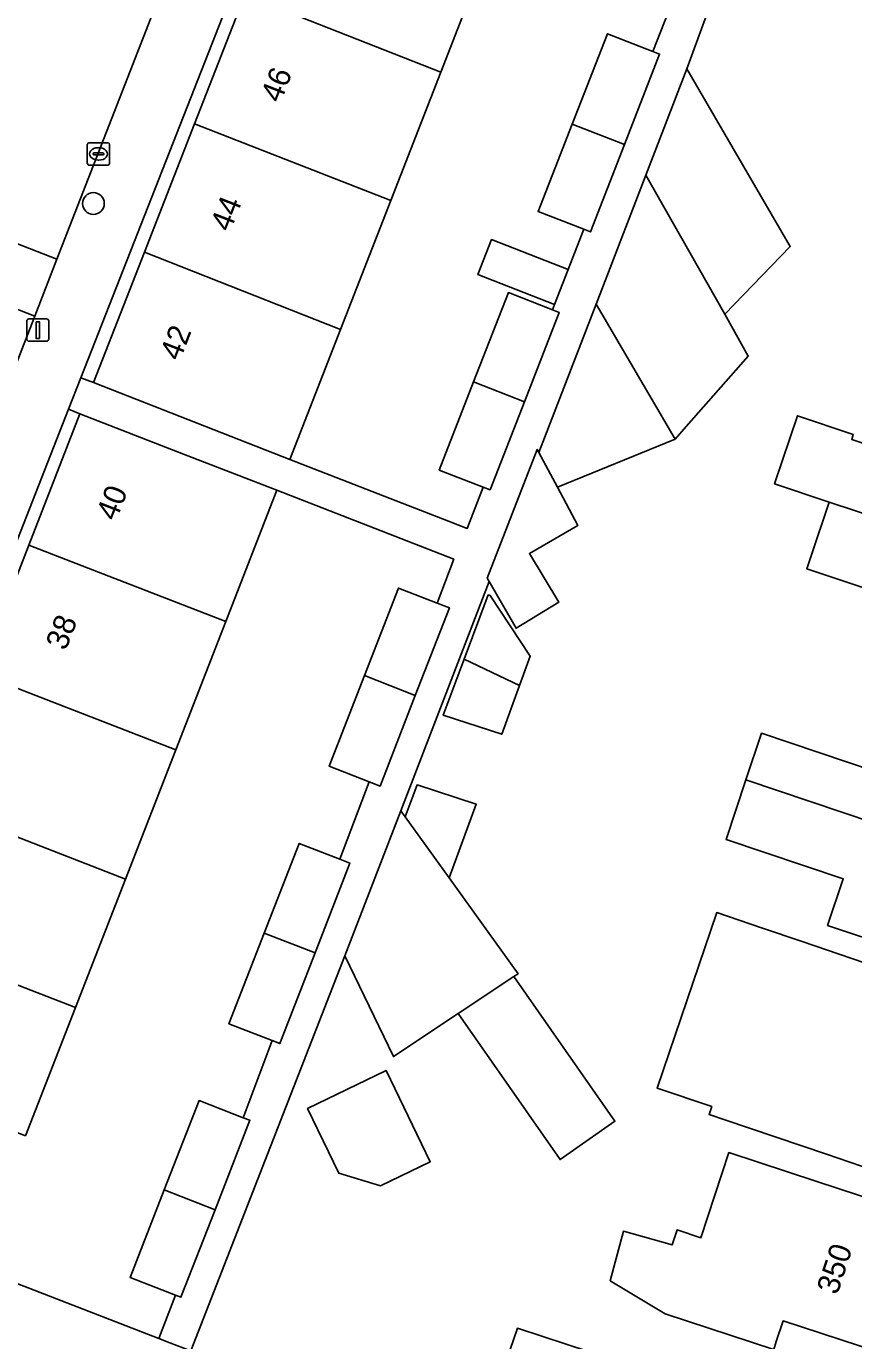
# Model space of a CAD drawing. Extents: x 161248 to 161848, y 384871 to 385383.
# Drawn here: x 161640.1 to 161677.3, y 385139.3 to 385198.5 of the extents above; entities that cross this region are included whole.
import ezdxf

# ---------------------------------------------------------------- set-up
doc = ezdxf.new("R2010")
doc.units = 0
for name, color, linetype in [('IMGEO_Boom', 7, 'Continuous'), ('IMGEO_Erf', 7, 'Continuous'), ('IMGEO_Kolk', 7, 'Continuous'), ('IMGEO_Lichtmast', 7, 'Continuous'), ('IMGEO_Pand', 7, 'Continuous'), ('IMGEO_Pand_nummerreeks', 7, 'Continuous'), ('IMGEO_Rijbaan_lokaal_open', 7, 'Continuous'), ('IMGEO_Voetpad_open', 7, 'Continuous')]:
    doc.layers.add(name, color=color, linetype=linetype)

msp = doc.modelspace()

# ---------------------------------------------------------------- linework, layer by layer
at = {"layer": 'IMGEO_Boom'}
msp.add_circle((161643.079, 385190.484), 0.489, dxfattribs=at)
at = {"layer": 'IMGEO_Erf'}
for points in [[(161654.386, 385211.393), (161656.644, 385217.179), (161658.899, 385222.955), (161661.19, 385228.826), (161658.366, 385229.85), (161658.187, 385226.898), (161657.602, 385223.032), (161656.675, 385219.233), (161655.412, 385215.533), (161642.519, 385182.649), (161643.081, 385182.429), (161645.371, 385188.297), (161647.622, 385194.063), (161649.884, 385199.859), (161652.083, 385205.494)], [(161637.929, 385169.353), (161640.175, 385175.123), (161642.475, 385181.032), (161641.964, 385181.232), (161628.283, 385146.338), (161628.877, 385146.101), (161631.173, 385151.999), (161633.419, 385157.768), (161635.668, 385163.546)], [(161662.244, 385168.813), (161661.44, 385166.618), (161658.808, 385167.475), (161659.748, 385169.996), (161660.827, 385172.886), (161660.921, 385172.851), (161662.724, 385170.122)], [(161656.239, 385151.494), (161658.225, 385147.394), (161655.988, 385146.311), (161654.119, 385146.88), (161652.712, 385149.785)]]:
    msp.add_lwpolyline(points, close=True, dxfattribs=at)
for points in [[(161675.04, 385210.948), (161669.768, 385196.541), (161674.417, 385188.547), (161671.465, 385185.506), (161672.515, 385183.615), (161669.733, 385180.456), (161669.236, 385179.891), (161663.947, 385177.724), (161664.866, 385176.006), (161662.688, 385174.743), (161664.001, 385172.555), (161662.085, 385171.383), (161660.87, 385173.48), (161656.896, 385163.18), (161657.099, 385162.898), (161657.636, 385164.335), (161660.29, 385163.477), (161659.073, 385160.158), (161662.176, 385155.85), (161661.989, 385155.726), (161666.53, 385149.215), (161664.061, 385147.492), (161659.481, 385154.059), (161656.566, 385152.122), (161654.38, 385156.66), (161647.453, 385138.885)], [(161660.94, 385202.148), (161658.696, 385196.386), (161656.448, 385190.614), (161654.193, 385184.823), (161651.916, 385178.978), (161659.042, 385176.194), (161659.88, 385175.866), (161660.608, 385177.73), (161658.632, 385178.499), (161660.177, 385182.466), (161661.739, 385186.476), (161663.723, 385185.703), (161663.816, 385185.941), (161660.368, 385187.284), (161660.983, 385188.864), (161664.431, 385187.521), (161665.132, 385189.323), (161663.077, 385190.123), (161664.609, 385194.056), (161666.191, 385198.118), (161668.241, 385197.319), (161669.584, 385200.772)], [(161680.453, 385172.283), (161675.16, 385174.052), (161675.327, 385174.553), (161676.163, 385177.056), (161673.709, 385177.876), (161674.732, 385180.937), (161677.249, 385180.096), (161677.175, 385179.873), (161682.375, 385178.135)], [(161637.729, 385142.655), (161646.017, 385139.442), (161646.773, 385141.392), (161644.734, 385142.186), (161646.268, 385146.127), (161647.832, 385150.145), (161649.815, 385149.373), (161651.114, 385152.845), (161649.176, 385153.599), (161650.764, 385157.677), (161652.334, 385161.709), (161654.164, 385160.996), (161655.481, 385164.475), (161653.683, 385165.175), (161655.271, 385169.254), (161656.803, 385173.19), (161658.533, 385172.517), (161659.281, 385174.489), (161651.327, 385177.586), (161649.028, 385171.681), (161646.782, 385165.911), (161644.522, 385160.104), (161642.272, 385154.325), (161640.026, 385148.555)], [(161679.112, 385157.009), (161676.089, 385158.024), (161676.793, 385160.12), (161671.526, 385161.889), (161672.423, 385164.561), (161673.128, 385166.659), (161678.281, 385164.927)], [(161680.771, 385146.118), (161676.038, 385147.728), (161671.476, 385149.279), (161670.764, 385149.522), (161670.883, 385149.872), (161668.426, 385150.708), (161671.111, 385158.6), (161673.114, 385157.918), (161674.951, 385157.293), (161678.841, 385155.97)], [(161673.673, 385138.958), (161668.79, 385140.562), (161666.321, 385142.043), (161666.91, 385144.269), (161667.285, 385144.164), (161669.102, 385143.655), (161669.323, 385144.33), (161670.397, 385143.977), (161671.654, 385147.805), (161675.604, 385146.508), (161680.354, 385144.948)], [(161661.28, 385137.38), (161662.143, 385139.909), (161667.621, 385138.111)], [(161678.348, 385138.839), (161674.092, 385140.237), (161673.787, 385139.306)]]:
    msp.add_lwpolyline(points, dxfattribs=at)
at = {"layer": 'IMGEO_Kolk'}
for p, q in [((161642.806, 385192.286), (161642.806, 385193.138)), ((161642.881, 385193.212), (161643.733, 385193.212)), ((161643.294, 385192.992), (161643.319, 385192.992)), ((161643.807, 385193.138), (161643.807, 385192.286)), ((161643.065, 385192.706), (161643.065, 385192.718)), ((161643.503, 385192.669), (161643.105, 385192.669)), ((161643.108, 385192.755), (161643.506, 385192.755)), ((161643.317, 385192.432), (161643.292, 385192.432)), ((161643.549, 385192.718), (161643.549, 385192.706)), ((161643.733, 385192.212), (161642.881, 385192.212))]:
    msp.add_line(p, q, dxfattribs=at)
for points in [[(161642.806, 385192.286), (161642.806, 385193.138)], [(161642.881, 385193.212), (161643.733, 385193.212)], [(161643.807, 385193.138), (161643.807, 385192.286)], [(161643.733, 385192.212), (161642.881, 385192.212)]]:
    msp.add_lwpolyline(points, dxfattribs=at)
for centre, radius, start, end in [((161642.883, 385193.136), 0.0765, 91.55205, 178.44795), ((161642.883, 385193.136), 0.0765, 91.55205, 178.44795), ((161643.731, 385193.136), 0.0765, 1.55205, 88.44795), ((161643.731, 385193.136), 0.0765, 1.55205, 88.44795), ((161643.105, 385192.715), 0.0403, 85.87752, 175.75265), ((161643.102, 385192.705), 0.0366, 178.93798, 274.71019), ((161643.506, 385192.712), 0.043, 264.86636, 352.45326), ((161643.51, 385192.717), 0.0386, 1.73085, 96.63898), ((161642.883, 385192.288), 0.0765, 181.55205, 268.44795), ((161642.883, 385192.288), 0.0765, 181.55205, 268.44795), ((161643.731, 385192.288), 0.0765, 271.55205, 358.44795), ((161643.731, 385192.288), 0.0765, 271.55205, 358.44795)]:
    msp.add_arc(centre, radius, start, end, dxfattribs=at)
for centre, major_axis, ratio, start_param, end_param in [((161643.293, 385192.712), (-0.387, 0.002), 0.722429, 4.712389, 7.853982), ((161643.318, 385192.712), (-0.39, 0.002), 0.717154, 1.570796, 4.712389)]:
    msp.add_ellipse(centre, major_axis=major_axis, ratio=ratio, start_param=start_param, end_param=end_param, dxfattribs=at)
at = {"layer": 'IMGEO_Lichtmast'}
for p, q in [((161640.182, 385185.292), (161640.972, 385185.292)), ((161640.972, 385185.292), (161640.182, 385185.292)), ((161640.082, 385184.392), (161640.082, 385185.192)), ((161640.082, 385185.192), (161640.082, 385184.392)), ((161641.072, 385185.192), (161641.072, 385184.392)), ((161641.072, 385184.392), (161641.072, 385185.192)), ((161640.972, 385184.292), (161640.182, 385184.292)), ((161640.182, 385184.292), (161640.972, 385184.292))]:
    msp.add_line(p, q, dxfattribs=at)
msp.add_lwpolyline([(161640.502, 385185.167), (161640.652, 385185.167), (161640.652, 385184.417), (161640.502, 385184.417), (161640.502, 385185.167)], dxfattribs=at)
for centre, start, end in [((161640.182, 385185.192), 90, 180), ((161640.182, 385185.192), 90, 180), ((161640.972, 385185.192), 0, 90), ((161640.972, 385185.192), 360, 90), ((161640.182, 385184.392), 180, 270), ((161640.182, 385184.392), 180, 270), ((161640.972, 385184.392), 270, 0), ((161640.972, 385184.392), 270, 0)]:
    msp.add_arc(centre, 0.1, start, end, dxfattribs=at)
at = {"layer": 'IMGEO_Pand'}
for points in [[(161652.083, 385205.494), (161649.884, 385199.859), (161658.696, 385196.386), (161660.94, 385202.148)], [(161656.448, 385190.614), (161658.696, 385196.386), (161649.884, 385199.859), (161647.622, 385194.063)], [(161668.241, 385197.319), (161666.191, 385198.118), (161664.609, 385194.056), (161666.954, 385193.131), (161668.539, 385197.203)], [(161671.465, 385185.506), (161674.417, 385188.547), (161669.768, 385196.541), (161667.922, 385191.755)], [(161647.622, 385194.063), (161645.371, 385188.297), (161654.193, 385184.823), (161656.448, 385190.614)], [(161666.954, 385193.131), (161664.609, 385194.056), (161663.077, 385190.123), (161665.132, 385189.323), (161665.426, 385189.208)], [(161667.922, 385191.755), (161666.013, 385186.808), (161665.684, 385185.956), (161669.236, 385179.891), (161669.733, 385180.456), (161672.515, 385183.615), (161671.465, 385185.506)], [(161664.431, 385187.521), (161660.983, 385188.864), (161660.368, 385187.284), (161663.816, 385185.941)], [(161645.371, 385188.297), (161643.081, 385182.429), (161647.739, 385180.61), (161651.916, 385178.978), (161654.193, 385184.823)], [(161663.723, 385185.703), (161661.739, 385186.476), (161660.177, 385182.466), (161662.459, 385181.568), (161664.024, 385185.586)], [(161669.236, 385179.891), (161665.684, 385185.956), (161663.111, 385179.288), (161663.947, 385177.724)], [(161662.459, 385181.568), (161660.177, 385182.466), (161658.632, 385178.499), (161660.608, 385177.73), (161660.918, 385177.609)], [(161691.577, 385178.551), (161686.835, 385180.135), (161683.424, 385181.275), (161682.375, 385178.135), (161677.175, 385179.873), (161677.249, 385180.096), (161674.732, 385180.937), (161673.709, 385177.876), (161676.163, 385177.056), (161689.598, 385172.63)], [(161649.028, 385171.681), (161651.327, 385177.586), (161647.135, 385179.218), (161642.475, 385181.032), (161640.175, 385175.123)], [(161663.947, 385177.724), (161663.111, 385179.288), (161663.036, 385179.428), (161660.78, 385173.636), (161660.87, 385173.48), (161662.085, 385171.383), (161664.001, 385172.555), (161662.688, 385174.743), (161664.866, 385176.006)], [(161689.598, 385172.63), (161676.163, 385177.056), (161675.327, 385174.553), (161675.16, 385174.052), (161680.453, 385172.283), (161679.498, 385169.423), (161682.877, 385168.294), (161687.619, 385166.709)], [(161640.175, 385175.123), (161637.929, 385169.353), (161646.782, 385165.911), (161649.028, 385171.681)], [(161658.533, 385172.517), (161656.803, 385173.19), (161655.271, 385169.254), (161657.555, 385168.366), (161659.087, 385172.301)], [(161660.827, 385172.886), (161659.748, 385169.996), (161662.244, 385168.813), (161662.724, 385170.122), (161660.921, 385172.851)], [(161662.244, 385168.813), (161659.748, 385169.996), (161658.808, 385167.475), (161661.44, 385166.618)], [(161644.522, 385160.104), (161646.782, 385165.911), (161637.929, 385169.353), (161635.668, 385163.546)], [(161657.555, 385168.366), (161655.271, 385169.254), (161653.683, 385165.175), (161655.481, 385164.475), (161655.967, 385164.286)], [(161687.053, 385164.948), (161682.314, 385166.54), (161679.177, 385167.594), (161678.281, 385164.927), (161673.128, 385166.659), (161672.423, 385164.561), (161685.452, 385160.182)], [(161685.452, 385160.182), (161672.423, 385164.561), (161671.526, 385161.889), (161676.793, 385160.12), (161676.089, 385158.024), (161679.112, 385157.009), (161683.851, 385155.417)], [(161660.29, 385163.477), (161657.636, 385164.335), (161657.099, 385162.898), (161659.073, 385160.158)], [(161642.272, 385154.325), (161644.522, 385160.104), (161635.668, 385163.546), (161633.419, 385157.768)], [(161659.073, 385160.158), (161657.099, 385162.898), (161656.896, 385163.18), (161654.38, 385156.66), (161656.566, 385152.122), (161659.481, 385154.059), (161661.989, 385155.726), (161662.176, 385155.85)], [(161654.164, 385160.996), (161652.334, 385161.709), (161650.764, 385157.677), (161653.048, 385156.789), (161654.617, 385160.82)], [(161683.574, 385154.36), (161678.841, 385155.97), (161674.951, 385157.293), (161673.114, 385157.918), (161671.111, 385158.6), (161668.426, 385150.708), (161670.883, 385149.872), (161670.764, 385149.522), (161671.476, 385149.279), (161676.038, 385147.728), (161680.771, 385146.118)], [(161640.026, 385148.555), (161642.272, 385154.325), (161633.419, 385157.768), (161631.173, 385151.999)], [(161653.048, 385156.789), (161650.764, 385157.677), (161649.176, 385153.599), (161651.114, 385152.845), (161651.46, 385152.71)], [(161661.989, 385155.726), (161659.481, 385154.059), (161664.061, 385147.492), (161666.53, 385149.215)], [(161654.119, 385146.88), (161655.988, 385146.311), (161658.225, 385147.394), (161656.239, 385151.494), (161652.712, 385149.785)], [(161649.815, 385149.373), (161647.832, 385150.145), (161646.268, 385146.127), (161648.552, 385145.238), (161650.116, 385149.256)], [(161680.354, 385144.948), (161675.604, 385146.508), (161671.654, 385147.805), (161670.397, 385143.977), (161669.323, 385144.33), (161669.102, 385143.655), (161667.285, 385144.164), (161666.91, 385144.269), (161666.321, 385142.043), (161668.79, 385140.562), (161673.673, 385138.958), (161673.787, 385139.306), (161674.092, 385140.237), (161678.348, 385138.839)], [(161648.552, 385145.238), (161646.268, 385146.127), (161644.734, 385142.186), (161646.773, 385141.392), (161647.018, 385141.297)], [(161674.738, 385128.314), (161676.989, 385134.917), (161672.257, 385136.53), (161667.621, 385138.111), (161662.143, 385139.909), (161661.28, 385137.38), (161665.676, 385135.882), (161664.715, 385133.063), (161664.837, 385133.005)]]:
    msp.add_lwpolyline(points, close=True, dxfattribs=at)
at = {"layer": 'IMGEO_Rijbaan_lokaal_open'}
msp.add_lwpolyline([(161646.477, 385219.731), (161642.948, 385210.8), (161635.004, 385190.489), (161641.438, 385187.982), (161648.956, 385207.28), (161652.424, 385216.415), (161653.708, 385220.298), (161654.641, 385224.281), (161655.214, 385228.331), (161655.423, 385232.416), (161655.402, 385234.118), (161654.91, 385250), (161654.892, 385250.594), (161647.135, 385250.394), (161647.167, 385250), (161648.501, 385233.307)], dxfattribs=at)
for points in [[(161640.44, 385185.42), (161641.438, 385187.982), (161635.004, 385190.489), (161634.002, 385187.929)], [(161640.44, 385185.42), (161634.002, 385187.929), (161620.865, 385154.341), (161616.012, 385142.32), (161616.144, 385142.272), (161622.644, 385139.739)]]:
    msp.add_lwpolyline(points, close=True, dxfattribs=at)
at = {"layer": 'IMGEO_Voetpad_open'}
for points in [[(161628.283, 385146.338), (161641.964, 385181.232), (161642.519, 385182.649), (161655.412, 385215.533)], [(161647.453, 385138.885), (161654.38, 385156.66), (161656.896, 385163.18), (161660.87, 385173.48), (161660.78, 385173.636), (161663.036, 385179.428), (161663.111, 385179.288), (161665.684, 385185.956), (161666.013, 385186.808), (161667.922, 385191.755), (161669.768, 385196.541), (161675.04, 385210.948)], [(161648.956, 385207.28), (161641.438, 385187.982), (161640.44, 385185.42), (161622.644, 385139.739)], [(161669.584, 385200.772), (161668.241, 385197.319), (161668.539, 385197.203), (161666.954, 385193.131), (161665.426, 385189.208), (161665.132, 385189.323), (161664.431, 385187.521), (161663.816, 385185.941), (161663.723, 385185.703), (161664.024, 385185.586), (161662.459, 385181.568), (161660.918, 385177.609), (161660.608, 385177.73), (161659.88, 385175.866), (161659.042, 385176.194), (161651.916, 385178.978), (161647.739, 385180.61), (161643.081, 385182.429), (161642.519, 385182.649), (161641.964, 385181.232), (161642.475, 385181.032), (161647.135, 385179.218), (161651.327, 385177.586), (161659.281, 385174.489), (161658.533, 385172.517), (161659.087, 385172.301), (161657.555, 385168.366), (161655.967, 385164.286), (161655.481, 385164.475), (161654.164, 385160.996), (161654.617, 385160.82), (161653.048, 385156.789), (161651.46, 385152.71), (161651.114, 385152.845), (161649.815, 385149.373), (161650.116, 385149.256), (161648.552, 385145.238), (161647.018, 385141.297), (161646.773, 385141.392), (161646.017, 385139.442), (161646.511, 385139.25)], [(161647.453, 385138.885), (161646.511, 385139.25), (161646.017, 385139.442), (161637.729, 385142.655), (161628.877, 385146.101), (161628.491, 385142.872), (161630.676, 385142.022), (161641.434, 385137.837), (161649.392, 385134.744), (161653.985, 385132.956), (161658.707, 385131.117), (161670.754, 385126.431), (161671.666, 385126.076)]]:
    msp.add_lwpolyline(points, dxfattribs=at)

# ---------------------------------------------------------------- texts
at = {"layer": 'IMGEO_Pand_nummerreeks'}
for s, rotation, p in [('46', 68.67903, (161651.495, 385194.966)), ('44', 68.67903, (161649.231, 385189.166)), ('42', 68.67903, (161646.966, 385183.363)), ('40', 68.72995, (161644.1, 385176.164)), ('38', 68.72995, (161641.834, 385170.342)), ('350', 71.82026, (161676.528, 385141.372))]:
    msp.add_text(s, height=1, rotation=rotation, dxfattribs=at).set_placement(p)

doc.saveas('drawing.dxf')
